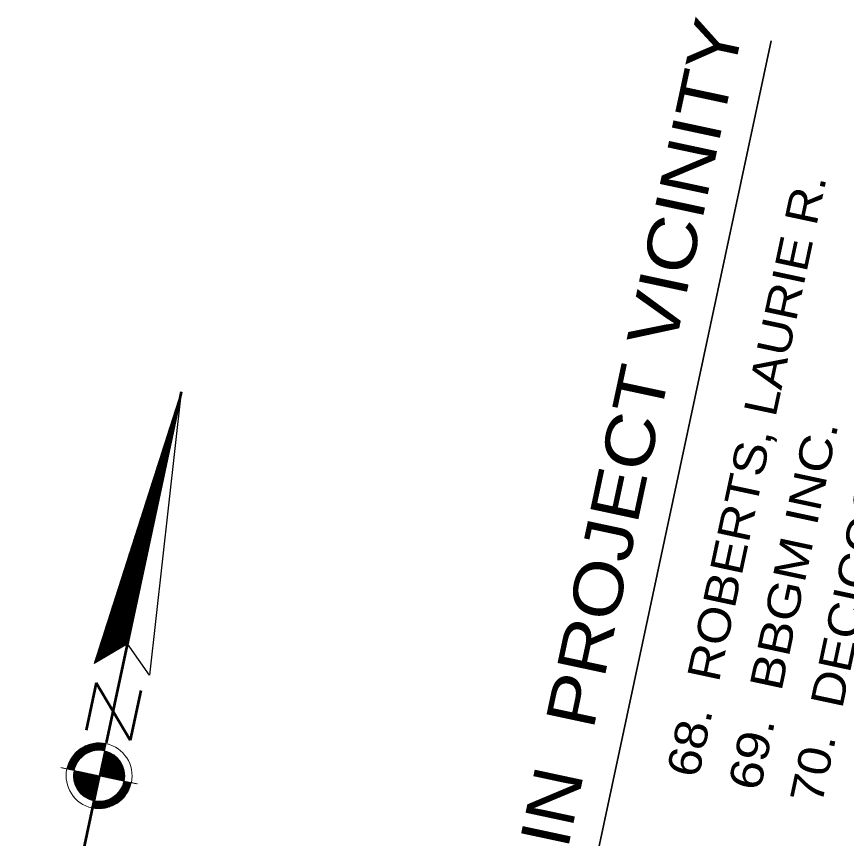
# Model space of a CAD drawing. Extents: x 2363411 to 2369702, y 6977197 to 6988655.
# Drawn here: x 2363737.9 to 2364093.2, y 6978563.1 to 6978914.9 of the extents above; entities that cross this region are included whole.
import ezdxf

# ---------------------------------------------------------------- set-up
doc = ezdxf.new("R2010")
doc.units = 0
doc.header["$LTSCALE"] = 5.6
doc.layers.add('1', color=7, linetype='Continuous', lineweight=25)
doc.layers.add('18', color=7, linetype='Continuous', lineweight=35)

msp = doc.modelspace()

# ---------------------------------------------------------------- linework, layer by layer
at = {"layer": '1', "lineweight": 53}
for p, q in [((2363808.35, 6978754.275), (2363776.257, 6978604.085)), ((2363772.027, 6978629.802), (2363767.673, 6978609.425)), ((2363772.027, 6978629.802), (2363786.549, 6978605.14)), ((2363791.108, 6978626.477), (2363786.549, 6978605.14)), ((2363773.247, 6978589.986), (2363737.89, 6978424.512))]:
    msp.add_line(p, q, dxfattribs=at)
at = {"layer": '1', "lineweight": 13}
for p, q in [((2363807.374, 6978751.23), (2363807.75, 6978751.475)), ((2363807.525, 6978751.705), (2363807.842, 6978751.909)), ((2363807.677, 6978752.18), (2363807.938, 6978752.345)), ((2363807.829, 6978752.648), (2363808.029, 6978752.781)), ((2363807.982, 6978753.125), (2363808.124, 6978753.215)), ((2363808.134, 6978753.598), (2363808.217, 6978753.651)), ((2363808.284, 6978754.071), (2363808.308, 6978754.088)), ((2363806.162, 6978747.443), (2363807.005, 6978747.987)), ((2363806.315, 6978747.918), (2363807.1, 6978748.425)), ((2363806.465, 6978748.391), (2363807.191, 6978748.862)), ((2363806.617, 6978748.864), (2363807.286, 6978749.297)), ((2363806.767, 6978749.337), (2363807.377, 6978749.732)), ((2363806.919, 6978749.81), (2363807.472, 6978750.166)), ((2363807.07, 6978750.285), (2363807.565, 6978750.602)), ((2363807.222, 6978750.757), (2363807.656, 6978751.039)), ((2363804.798, 6978743.182), (2363806.169, 6978744.069)), ((2363804.948, 6978743.655), (2363806.263, 6978744.505)), ((2363805.102, 6978744.13), (2363806.353, 6978744.938)), ((2363805.253, 6978744.603), (2363806.449, 6978745.378)), ((2363805.405, 6978745.075), (2363806.54, 6978745.812)), ((2363805.553, 6978745.549), (2363806.635, 6978746.248)), ((2363805.707, 6978746.021), (2363806.726, 6978746.683)), ((2363805.86, 6978746.496), (2363806.821, 6978747.117)), ((2363806.01, 6978746.971), (2363806.914, 6978747.555)), ((2363803.585, 6978739.394), (2363805.422, 6978740.582)), ((2363803.737, 6978739.866), (2363805.518, 6978741.02)), ((2363803.89, 6978740.339), (2363805.611, 6978741.454)), ((2363804.038, 6978740.813), (2363805.702, 6978741.891)), ((2363804.19, 6978741.285), (2363805.797, 6978742.326)), ((2363804.342, 6978741.76), (2363805.888, 6978742.763)), ((2363804.495, 6978742.233), (2363805.983, 6978743.199)), ((2363804.647, 6978742.707), (2363806.075, 6978743.635)), ((2363802.373, 6978735.605), (2363804.68, 6978737.1)), ((2363802.523, 6978736.078), (2363804.771, 6978737.535)), ((2363802.678, 6978736.553), (2363804.866, 6978737.971)), ((2363802.828, 6978737.026), (2363804.959, 6978738.407)), ((2363802.978, 6978737.499), (2363805.05, 6978738.841)), ((2363803.13, 6978737.971), (2363805.145, 6978739.277)), ((2363803.281, 6978738.446), (2363805.236, 6978739.712)), ((2363803.435, 6978738.919), (2363805.332, 6978740.15)), ((2363801.161, 6978731.817), (2363803.934, 6978733.615)), ((2363801.311, 6978732.292), (2363804.028, 6978734.049)), ((2363801.461, 6978732.763), (2363804.12, 6978734.486)), ((2363801.613, 6978733.238), (2363804.215, 6978734.921)), ((2363801.768, 6978733.71), (2363804.306, 6978735.356)), ((2363801.918, 6978734.185), (2363804.399, 6978735.792)), ((2363802.071, 6978734.66), (2363804.494, 6978736.23)), ((2363802.221, 6978735.133), (2363804.585, 6978736.664)), ((2363799.948, 6978728.028), (2363803.191, 6978730.129)), ((2363800.098, 6978728.501), (2363803.283, 6978730.568)), ((2363800.251, 6978728.976), (2363803.377, 6978731.002)), ((2363800.401, 6978729.449), (2363803.47, 6978731.438)), ((2363800.554, 6978729.924), (2363803.563, 6978731.872)), ((2363800.706, 6978730.398), (2363803.654, 6978732.307)), ((2363800.856, 6978730.871), (2363803.748, 6978732.747)), ((2363801.008, 6978731.344), (2363803.842, 6978733.179)), ((2363798.736, 6978724.24), (2363802.445, 6978726.646)), ((2363798.886, 6978724.713), (2363802.539, 6978727.08)), ((2363799.036, 6978725.186), (2363802.631, 6978727.518)), ((2363799.189, 6978725.661), (2363802.725, 6978727.95)), ((2363799.341, 6978726.133), (2363802.819, 6978728.388)), ((2363799.491, 6978726.608), (2363802.912, 6978728.823)), ((2363799.644, 6978727.083), (2363803.003, 6978729.259)), ((2363799.794, 6978727.558), (2363803.096, 6978729.695)), ((2363797.372, 6978719.981), (2363801.608, 6978722.722)), ((2363797.522, 6978720.454), (2363801.7, 6978723.163)), ((2363797.674, 6978720.924), (2363801.793, 6978723.597)), ((2363797.824, 6978721.399), (2363801.888, 6978724.033)), ((2363797.977, 6978721.874), (2363801.979, 6978724.467)), ((2363798.129, 6978722.347), (2363802.074, 6978724.903)), ((2363798.281, 6978722.821), (2363802.167, 6978725.339)), ((2363798.432, 6978723.295), (2363802.26, 6978725.773)), ((2363798.584, 6978723.767), (2363802.351, 6978726.21)), ((2363796.159, 6978716.19), (2363800.864, 6978719.239)), ((2363796.309, 6978716.665), (2363800.957, 6978719.675)), ((2363796.464, 6978717.138), (2363801.048, 6978720.111)), ((2363796.612, 6978717.613), (2363801.141, 6978720.546)), ((2363796.766, 6978718.085), (2363801.236, 6978720.981)), ((2363796.917, 6978718.56), (2363801.327, 6978721.418)), ((2363797.067, 6978719.033), (2363801.422, 6978721.852)), ((2363797.221, 6978719.506), (2363801.516, 6978722.29)), ((2363794.946, 6978712.402), (2363800.12, 6978715.755)), ((2363795.097, 6978712.877), (2363800.213, 6978716.191)), ((2363795.249, 6978713.349), (2363800.306, 6978716.625)), ((2363795.399, 6978713.823), (2363800.397, 6978717.062)), ((2363795.552, 6978714.297), (2363800.49, 6978717.496)), ((2363795.704, 6978714.772), (2363800.585, 6978717.934)), ((2363795.855, 6978715.245), (2363800.676, 6978718.369)), ((2363796.005, 6978715.718), (2363800.771, 6978718.804)), ((2363793.734, 6978708.613), (2363799.373, 6978712.27)), ((2363793.885, 6978709.088), (2363799.468, 6978712.706)), ((2363794.035, 6978709.563), (2363799.561, 6978713.14)), ((2363794.188, 6978710.038), (2363799.654, 6978713.576)), ((2363794.338, 6978710.511), (2363799.745, 6978714.013)), ((2363794.49, 6978710.984), (2363799.838, 6978714.449)), ((2363794.642, 6978711.456), (2363799.934, 6978714.885)), ((2363794.794, 6978711.929), (2363800.024, 6978715.319)), ((2363792.52, 6978704.827), (2363798.63, 6978708.786)), ((2363792.672, 6978705.3), (2363798.721, 6978709.221)), ((2363792.823, 6978705.775), (2363798.816, 6978709.656)), ((2363792.977, 6978706.247), (2363798.909, 6978710.091)), ((2363793.128, 6978706.722), (2363799.003, 6978710.529)), ((2363793.279, 6978707.193), (2363799.094, 6978710.963)), ((2363793.43, 6978707.668), (2363799.187, 6978711.4)), ((2363793.58, 6978708.141), (2363799.282, 6978711.833)), ((2363791.31, 6978701.038), (2363797.884, 6978705.303)), ((2363791.46, 6978701.513), (2363797.979, 6978705.735)), ((2363791.61, 6978701.986), (2363798.07, 6978706.171)), ((2363791.763, 6978702.461), (2363798.164, 6978706.605)), ((2363791.915, 6978702.934), (2363798.258, 6978707.041)), ((2363792.065, 6978703.407), (2363798.351, 6978707.478)), ((2363792.218, 6978703.881), (2363798.442, 6978707.912)), ((2363792.368, 6978704.355), (2363798.535, 6978708.35)), ((2363790.094, 6978697.253), (2363797.139, 6978701.817)), ((2363790.248, 6978697.725), (2363797.232, 6978702.252)), ((2363790.398, 6978698.198), (2363797.327, 6978702.685)), ((2363790.551, 6978698.673), (2363797.419, 6978703.124)), ((2363790.703, 6978699.145), (2363797.513, 6978703.558)), ((2363790.853, 6978699.618), (2363797.607, 6978703.994)), ((2363791.007, 6978700.091), (2363797.699, 6978704.428)), ((2363791.156, 6978700.566), (2363797.79, 6978704.863)), ((2363788.733, 6978692.989), (2363796.303, 6978697.895)), ((2363788.882, 6978693.466), (2363796.394, 6978698.33)), ((2363789.034, 6978693.937), (2363796.488, 6978698.766)), ((2363789.186, 6978694.411), (2363796.581, 6978699.202)), ((2363789.337, 6978694.886), (2363796.675, 6978699.636)), ((2363789.49, 6978695.357), (2363796.767, 6978700.075)), ((2363789.641, 6978695.83), (2363796.862, 6978700.508)), ((2363789.793, 6978696.303), (2363796.955, 6978700.945)), ((2363789.945, 6978696.777), (2363797.046, 6978701.379)), ((2363787.521, 6978689.202), (2363795.559, 6978694.41)), ((2363787.669, 6978689.676), (2363795.652, 6978694.846)), ((2363787.824, 6978690.15), (2363795.743, 6978695.281)), ((2363787.973, 6978690.621), (2363795.836, 6978695.719)), ((2363788.126, 6978691.096), (2363795.929, 6978696.153)), ((2363788.278, 6978691.57), (2363796.024, 6978696.589)), ((2363788.429, 6978692.043), (2363796.115, 6978697.023)), ((2363788.579, 6978692.516), (2363796.21, 6978697.459)), ((2363786.306, 6978685.412), (2363794.812, 6978690.925)), ((2363786.459, 6978685.887), (2363794.907, 6978691.361)), ((2363786.609, 6978686.362), (2363795, 6978691.797)), ((2363786.761, 6978686.834), (2363795.092, 6978692.233)), ((2363786.913, 6978687.307), (2363795.185, 6978692.671)), ((2363787.064, 6978687.78), (2363795.278, 6978693.104)), ((2363787.216, 6978688.255), (2363795.373, 6978693.539)), ((2363787.366, 6978688.728), (2363795.464, 6978693.976)), ((2363785.094, 6978681.626), (2363794.07, 6978687.441)), ((2363785.244, 6978682.099), (2363794.161, 6978687.875)), ((2363785.396, 6978682.571), (2363794.256, 6978688.313)), ((2363785.549, 6978683.048), (2363794.349, 6978688.747)), ((2363785.699, 6978683.517), (2363794.44, 6978689.184)), ((2363785.849, 6978683.992), (2363794.533, 6978689.618)), ((2363786.004, 6978684.466), (2363794.626, 6978690.052)), ((2363786.156, 6978684.941), (2363794.721, 6978690.49)), ((2363783.878, 6978677.84), (2363793.323, 6978683.956)), ((2363784.035, 6978678.314), (2363793.418, 6978684.392)), ((2363784.182, 6978678.785), (2363793.509, 6978684.826)), ((2363784.337, 6978679.259), (2363793.605, 6978685.264)), ((2363784.487, 6978679.733), (2363793.697, 6978685.696)), ((2363784.637, 6978680.206), (2363793.788, 6978686.133)), ((2363784.792, 6978680.68), (2363793.882, 6978686.571)), ((2363784.942, 6978681.153), (2363793.974, 6978687.003)), ((2363782.667, 6978674.049), (2363792.578, 6978680.47)), ((2363782.82, 6978674.522), (2363792.671, 6978680.906)), ((2363782.972, 6978674.996), (2363792.767, 6978681.342)), ((2363783.122, 6978675.469), (2363792.857, 6978681.777)), ((2363783.275, 6978675.946), (2363792.953, 6978682.215)), ((2363783.425, 6978676.419), (2363793.045, 6978682.647)), ((2363783.577, 6978676.892), (2363793.137, 6978683.085)), ((2363783.73, 6978677.364), (2363793.23, 6978683.52)), ((2363781.305, 6978669.789), (2363791.743, 6978676.55)), ((2363781.455, 6978670.261), (2363791.834, 6978676.987)), ((2363781.608, 6978670.735), (2363791.929, 6978677.421)), ((2363781.76, 6978671.208), (2363792.02, 6978677.859)), ((2363781.91, 6978671.681), (2363792.115, 6978678.293)), ((2363782.06, 6978672.156), (2363792.206, 6978678.73)), ((2363782.213, 6978672.629), (2363792.301, 6978679.165)), ((2363782.365, 6978673.103), (2363792.394, 6978679.599)), ((2363782.517, 6978673.576), (2363792.485, 6978680.036)), ((2363780.091, 6978666.001), (2363790.998, 6978673.065)), ((2363780.243, 6978666.474), (2363791.092, 6978673.503)), ((2363780.393, 6978666.945), (2363791.182, 6978673.937)), ((2363780.547, 6978667.419), (2363791.278, 6978674.373)), ((2363780.696, 6978667.895), (2363791.369, 6978674.81)), ((2363780.848, 6978668.368), (2363791.464, 6978675.244)), ((2363781.003, 6978668.842), (2363791.555, 6978675.68)), ((2363781.153, 6978669.315), (2363791.65, 6978676.116)), ((2363778.877, 6978662.213), (2363790.251, 6978669.58)), ((2363779.031, 6978662.688), (2363790.346, 6978670.015)), ((2363779.181, 6978663.161), (2363790.44, 6978670.452)), ((2363779.333, 6978663.633), (2363790.53, 6978670.886)), ((2363779.485, 6978664.106), (2363790.626, 6978671.322)), ((2363779.638, 6978664.579), (2363790.717, 6978671.759)), ((2363779.791, 6978665.055), (2363790.812, 6978672.192)), ((2363779.941, 6978665.528), (2363790.903, 6978672.631)), ((2363777.664, 6978658.425), (2363789.509, 6978666.096)), ((2363777.818, 6978658.897), (2363789.6, 6978666.532)), ((2363777.969, 6978659.372), (2363789.695, 6978666.966)), ((2363778.121, 6978659.845), (2363789.786, 6978667.403)), ((2363778.272, 6978660.32), (2363789.879, 6978667.839)), ((2363778.424, 6978660.793), (2363789.974, 6978668.275)), ((2363778.576, 6978661.267), (2363790.065, 6978668.709)), ((2363778.726, 6978661.738), (2363790.16, 6978669.145)), ((2363776.452, 6978654.636), (2363788.762, 6978662.611)), ((2363776.604, 6978655.109), (2363788.858, 6978663.048)), ((2363776.756, 6978655.582), (2363788.949, 6978663.483)), ((2363776.907, 6978656.057), (2363789.043, 6978663.917)), ((2363777.061, 6978656.529), (2363789.135, 6978664.353)), ((2363777.211, 6978657.004), (2363789.228, 6978664.79)), ((2363777.363, 6978657.477), (2363789.323, 6978665.225)), ((2363777.516, 6978657.949), (2363789.414, 6978665.66)), ((2363775.239, 6978650.848), (2363788.02, 6978659.127)), ((2363775.393, 6978651.32), (2363788.111, 6978659.563)), ((2363775.544, 6978651.795), (2363788.206, 6978659.997)), ((2363775.695, 6978652.27), (2363788.299, 6978660.433)), ((2363775.847, 6978652.743), (2363788.392, 6978660.867)), ((2363775.999, 6978653.218), (2363788.483, 6978661.304)), ((2363776.151, 6978653.688), (2363788.577, 6978661.742)), ((2363776.304, 6978654.163), (2363788.672, 6978662.178)), ((2363774.029, 6978647.061), (2363787.273, 6978655.642)), ((2363774.18, 6978647.536), (2363787.368, 6978656.075)), ((2363774.332, 6978648.007), (2363787.459, 6978656.512)), ((2363774.482, 6978648.482), (2363787.554, 6978656.948)), ((2363774.635, 6978648.956), (2363787.647, 6978657.384)), ((2363774.787, 6978649.429), (2363787.741, 6978657.82)), ((2363774.937, 6978649.902), (2363787.832, 6978658.257)), ((2363775.091, 6978650.372), (2363787.925, 6978658.691)), ((2363772.664, 6978642.798), (2363786.438, 6978651.721)), ((2363772.817, 6978643.271), (2363786.528, 6978652.156)), ((2363772.967, 6978643.746), (2363786.622, 6978652.592)), ((2363773.117, 6978644.219), (2363786.716, 6978653.026)), ((2363773.27, 6978644.693), (2363786.808, 6978653.465)), ((2363773.422, 6978645.166), (2363786.903, 6978653.9)), ((2363773.575, 6978645.641), (2363786.996, 6978654.335)), ((2363773.727, 6978646.113), (2363787.089, 6978654.771)), ((2363773.877, 6978646.586), (2363787.18, 6978655.203)), ((2363771.45, 6978639.01), (2363785.693, 6978648.238)), ((2363771.605, 6978639.484), (2363785.786, 6978648.672)), ((2363771.755, 6978639.957), (2363785.877, 6978649.109)), ((2363771.907, 6978640.432), (2363785.97, 6978649.545)), ((2363772.057, 6978640.905), (2363786.065, 6978649.977)), ((2363772.21, 6978641.378), (2363786.156, 6978650.415)), ((2363772.36, 6978641.851), (2363786.251, 6978650.849)), ((2363772.512, 6978642.323), (2363786.344, 6978651.285)), ((2363771.147, 6978638.062), (2363785.505, 6978647.366)), ((2363771.3, 6978638.537), (2363785.6, 6978647.8)), ((2363777.979, 6978642.112), (2363785.414, 6978646.929)), ((2363759.909, 6978594.501), (2363774.54, 6978603.982)), ((2363760.085, 6978594.991), (2363774.02, 6978604.019)), ((2363760.294, 6978595.5), (2363773.472, 6978604.04)), ((2363760.532, 6978596.03), (2363772.888, 6978604.034)), ((2363760.815, 6978596.588), (2363772.263, 6978604.008)), ((2363761.146, 6978597.182), (2363771.586, 6978603.942)), ((2363761.547, 6978597.814), (2363770.843, 6978603.837)), ((2363762.06, 6978598.52), (2363769.993, 6978603.665)), ((2363762.724, 6978599.327), (2363768.99, 6978603.384)), ((2363763.763, 6978600.373), (2363767.6, 6978602.863)), ((2363769.083, 6978600.069), (2363775.035, 6978603.927)), ((2363770.324, 6978600.497), (2363775.511, 6978603.858)), ((2363771.221, 6978600.702), (2363775.962, 6978603.776)), ((2363771.976, 6978600.819), (2363776.135, 6978603.514)), ((2363772.642, 6978600.873), (2363776.041, 6978603.076)), ((2363773.247, 6978600.889), (2363775.949, 6978602.641)), ((2363773.804, 6978600.876), (2363775.858, 6978602.207)), ((2363776.183, 6978603.731), (2363775.526, 6978600.652)), ((2363774.236, 6978594.626), (2363780.13, 6978598.445)), ((2363774.322, 6978600.838), (2363775.765, 6978601.771)), ((2363774.332, 6978595.064), (2363779.869, 6978598.65)), ((2363774.422, 6978595.498), (2363779.599, 6978598.851)), ((2363774.518, 6978595.934), (2363779.32, 6978599.048)), ((2363774.61, 6978596.368), (2363779.029, 6978599.233)), ((2363774.704, 6978596.805), (2363778.728, 6978599.413)), ((2363774.795, 6978597.243), (2363778.417, 6978599.588)), ((2363774.808, 6978600.777), (2363775.67, 6978601.337)), ((2363774.888, 6978597.675), (2363778.093, 6978599.754)), ((2363774.983, 6978598.111), (2363777.76, 6978599.911)), ((2363775.074, 6978598.548), (2363777.414, 6978600.06)), ((2363775.169, 6978598.983), (2363777.054, 6978600.205)), ((2363775.262, 6978599.418), (2363776.677, 6978600.334)), ((2363775.272, 6978600.698), (2363775.578, 6978600.898)), ((2363775.355, 6978599.854), (2363776.283, 6978600.455)), ((2363775.446, 6978600.29), (2363775.876, 6978600.567)), ((2363759.514, 6978593.121), (2363764.257, 6978596.194)), ((2363759.623, 6978593.566), (2363764.817, 6978596.931)), ((2363759.682, 6978592.854), (2363763.838, 6978595.545)), ((2363759.754, 6978594.025), (2363765.701, 6978597.879)), ((2363760.118, 6978592.761), (2363763.517, 6978594.961)), ((2363773.308, 6978590.272), (2363782.291, 6978596.094)), ((2363773.36, 6978589.931), (2363782.461, 6978595.828)), ((2363773.4, 6978590.706), (2363782.108, 6978596.349)), ((2363773.492, 6978591.144), (2363781.919, 6978596.604)), ((2363773.585, 6978591.579), (2363781.727, 6978596.852)), ((2363773.68, 6978592.014), (2363781.521, 6978597.096)), ((2363773.771, 6978592.449), (2363781.31, 6978597.334)), ((2363773.796, 6978589.838), (2363782.629, 6978595.561)), ((2363773.866, 6978592.887), (2363781.09, 6978597.567)), ((2363773.959, 6978593.319), (2363780.863, 6978597.796)), ((2363774.052, 6978593.757), (2363780.628, 6978598.017)), ((2363774.143, 6978594.192), (2363780.384, 6978598.233)), ((2363774.23, 6978589.743), (2363782.785, 6978595.286)), ((2363774.668, 6978589.652), (2363782.936, 6978595.009)), ((2363759.484, 6978592.896), (2363756.771, 6978593.474)), ((2363757.127, 6978593.4), (2363783.865, 6978587.687)), ((2363762.543, 6978592.242), (2363759.463, 6978592.901)), ((2363760.552, 6978592.668), (2363763.256, 6978594.418)), ((2363760.99, 6978592.574), (2363763.043, 6978593.903)), ((2363761.425, 6978592.481), (2363762.866, 6978593.415)), ((2363761.861, 6978592.388), (2363762.721, 6978592.947)), ((2363765.207, 6978591.673), (2363762.235, 6978589.748)), ((2363764.771, 6978591.766), (2363762.238, 6978590.123)), ((2363764.337, 6978591.859), (2363762.248, 6978590.508)), ((2363765.643, 6978591.578), (2363762.251, 6978589.382)), ((2363763.903, 6978591.952), (2363762.27, 6978590.898)), ((2363766.08, 6978591.487), (2363762.277, 6978589.023)), ((2363762.297, 6978592.293), (2363762.601, 6978592.492)), ((2363766.516, 6978591.394), (2363762.312, 6978588.67)), ((2363763.465, 6978592.046), (2363762.313, 6978591.3)), ((2363766.952, 6978591.3), (2363762.359, 6978588.324)), ((2363763.03, 6978592.138), (2363762.375, 6978591.714)), ((2363762.594, 6978592.23), (2363762.452, 6978592.139)), ((2363789.283, 6978586.529), (2363762.543, 6978592.242)), ((2363775.102, 6978589.559), (2363783.081, 6978594.726)), ((2363775.537, 6978589.466), (2363783.213, 6978594.438)), ((2363775.975, 6978589.373), (2363783.341, 6978594.145)), ((2363776.407, 6978589.28), (2363783.459, 6978593.848)), ((2363776.845, 6978589.187), (2363783.568, 6978593.542)), ((2363777.279, 6978589.092), (2363783.674, 6978593.233)), ((2363777.716, 6978589.001), (2363783.764, 6978592.919)), ((2363778.152, 6978588.907), (2363783.849, 6978592.599)), ((2363778.586, 6978588.815), (2363783.927, 6978592.273)), ((2363779.022, 6978588.721), (2363783.993, 6978591.94)), ((2363779.458, 6978588.628), (2363784.051, 6978591.602)), ((2363767.386, 6978591.208), (2363762.416, 6978587.989)), ((2363767.822, 6978591.114), (2363762.479, 6978587.654)), ((2363768.257, 6978591.022), (2363762.559, 6978587.328)), ((2363768.692, 6978590.927), (2363762.644, 6978587.01)), ((2363769.129, 6978590.835), (2363762.736, 6978586.693)), ((2363769.563, 6978590.742), (2363762.839, 6978586.387)), ((2363769.999, 6978590.649), (2363762.949, 6978586.081)), ((2363770.436, 6978590.556), (2363763.067, 6978585.78)), ((2363770.87, 6978590.463), (2363763.197, 6978585.489)), ((2363771.308, 6978590.37), (2363763.328, 6978585.203)), ((2363771.74, 6978590.275), (2363763.474, 6978584.918)), ((2363772.176, 6978590.184), (2363763.623, 6978584.641)), ((2363772.613, 6978590.091), (2363763.779, 6978584.366)), ((2363773.049, 6978589.998), (2363763.945, 6978584.101)), ((2363773.103, 6978589.657), (2363764.115, 6978583.834)), ((2363773.01, 6978589.223), (2363764.298, 6978583.578)), ((2363772.917, 6978588.787), (2363764.489, 6978583.323)), ((2363772.824, 6978588.352), (2363764.681, 6978583.075)), ((2363772.73, 6978587.912), (2363764.887, 6978582.833)), ((2363773.17, 6978589.972), (2363773.072, 6978589.993)), ((2363773.238, 6978589.957), (2363773.336, 6978589.936)), ((2363779.895, 6978588.535), (2363784.097, 6978591.259)), ((2363780.33, 6978588.44), (2363784.13, 6978590.907)), ((2363780.765, 6978588.349), (2363784.159, 6978590.546)), ((2363781.201, 6978588.256), (2363784.173, 6978590.179)), ((2363781.635, 6978588.163), (2363784.172, 6978589.803)), ((2363782.073, 6978588.069), (2363784.16, 6978589.423)), ((2363782.508, 6978587.977), (2363784.136, 6978589.032)), ((2363782.944, 6978587.883), (2363784.095, 6978588.629)), ((2363783.38, 6978587.788), (2363784.033, 6978588.215)), ((2363783.814, 6978587.698), (2363783.959, 6978587.791)), ((2363772.638, 6978587.48), (2363765.098, 6978582.593)), ((2363772.544, 6978587.044), (2363765.318, 6978582.36)), ((2363772.451, 6978586.608), (2363765.546, 6978582.134)), ((2363772.358, 6978586.171), (2363765.782, 6978581.911)), ((2363772.263, 6978585.736), (2363766.026, 6978581.693)), ((2363772.172, 6978585.299), (2363766.28, 6978581.484)), ((2363772.078, 6978584.863), (2363766.54, 6978581.275)), ((2363771.986, 6978584.429), (2363766.811, 6978581.078)), ((2363786.502, 6978585.43), (2363771.871, 6978575.947)), ((2363786.323, 6978584.938), (2363772.389, 6978575.91)), ((2363786.116, 6978584.426), (2363772.936, 6978575.889)), ((2363786.654, 6978585.904), (2363780.705, 6978582.05)), ((2363786.785, 6978586.363), (2363781.591, 6978582.998)), ((2363786.895, 6978586.808), (2363782.151, 6978583.733)), ((2363786.724, 6978587.074), (2363782.57, 6978584.382)), ((2363786.29, 6978587.168), (2363782.893, 6978584.966)), ((2363785.854, 6978587.262), (2363783.152, 6978585.509)), ((2363785.418, 6978587.355), (2363783.367, 6978586.024)), ((2363784.984, 6978587.448), (2363783.541, 6978586.512)), ((2363784.548, 6978587.541), (2363783.686, 6978586.984)), ((2363784.112, 6978587.634), (2363783.807, 6978587.435)), ((2363783.865, 6978587.687), (2363786.946, 6978587.028)), ((2363786.924, 6978587.033), (2363789.639, 6978586.453)), ((2363771.893, 6978583.994), (2363767.088, 6978580.882)), ((2363771.799, 6978583.556), (2363767.38, 6978580.695)), ((2363771.707, 6978583.124), (2363767.68, 6978580.514)), ((2363771.611, 6978582.686), (2363767.989, 6978580.339)), ((2363771.52, 6978582.252), (2363768.313, 6978580.174)), ((2363771.427, 6978581.816), (2363768.65, 6978580.016)), ((2363771.334, 6978581.379), (2363768.996, 6978579.864)), ((2363771.241, 6978580.945), (2363769.356, 6978579.722)), ((2363785.876, 6978583.897), (2363773.518, 6978575.894)), ((2363785.593, 6978583.337), (2363774.146, 6978575.921)), ((2363785.26, 6978582.748), (2363774.822, 6978575.985)), ((2363784.861, 6978582.113), (2363775.565, 6978576.094)), ((2363784.35, 6978581.406), (2363776.415, 6978576.269)), ((2363771.148, 6978580.509), (2363769.731, 6978579.593)), ((2363771.055, 6978580.075), (2363770.123, 6978579.472)), ((2363770.227, 6978576.196), (2363770.885, 6978579.277)), ((2363774.43, 6978579.108), (2363770.273, 6978576.413)), ((2363773.766, 6978579.054), (2363770.367, 6978576.851)), ((2363775.189, 6978579.224), (2363770.446, 6978576.153)), ((2363773.161, 6978579.038), (2363770.46, 6978577.288)), ((2363770.96, 6978579.639), (2363770.53, 6978579.361)), ((2363772.604, 6978579.053), (2363770.553, 6978577.722)), ((2363772.086, 6978579.09), (2363770.646, 6978578.158)), ((2363771.596, 6978579.151), (2363770.739, 6978578.592)), ((2363771.138, 6978579.229), (2363770.832, 6978579.028)), ((2363776.086, 6978579.429), (2363770.897, 6978576.071)), ((2363777.323, 6978579.858), (2363771.371, 6978576.003)), ((2363783.684, 6978580.6), (2363777.42, 6978576.543)), ((2363782.647, 6978579.553), (2363778.806, 6978577.065))]:
    msp.add_line(p, q, dxfattribs=at)
msp.add_lwpolyline([(2363771.137, 6978638.025), (2363785.32, 6978646.5), (2363808.35, 6978754.275)], close=True, dxfattribs=at)
at = {"layer": '1'}
msp.add_lwpolyline([(2363794.805, 6978632.97), (2363785.32, 6978646.5), (2363808.35, 6978754.275)], close=True, dxfattribs=at)
at = {"layer": '1', "lineweight": 13}
for points in [[(2363783.935, 6978587.67), (2363773.238, 6978589.957), (2363775.526, 6978600.652)], [(2363762.473, 6978592.257), (2363773.17, 6978589.972), (2363770.885, 6978579.277)]]:
    msp.add_lwpolyline(points, dxfattribs=at)
for centre, radius, start, end in [((2363773.239, 6978589.956), 14.087, 77.93906, 167.93906), ((2363773.239, 6978589.956), 14.087, 347.93906, 77.75402), ((2363773.239, 6978589.956), 10.937, 77.93906, 167.93906), ((2363773.239, 6978589.956), 10.937, 347.93906, 77.93906), ((2363773.169, 6978589.971), 14.087, 167.93906, 257.75402), ((2363773.169, 6978589.971), 10.937, 167.93906, 257.93906), ((2363773.169, 6978589.971), 14.087, 257.93906, 347.93906), ((2363773.169, 6978589.971), 10.937, 257.93906, 347.93906)]:
    msp.add_arc(centre, radius, start, end, dxfattribs=at)
at = {"layer": '18'}
msp.add_line((2363910.069, 6978198.379), (2364060.962, 6978904.578), dxfattribs=at)

# ---------------------------------------------------------------- texts
for s, height, width, p in [('PROPERTY OWNERS IN  PROJECT VICINITY', 21, 1.2, (2363899.459, 6978210.017)), ('68.  ROBERTS, LAURIE R.', 14, 1.15, (2364029.752, 6978588.555)), ('70.  DECICCO, PETER A.', 14, 1.15, (2364082.561, 6978577.272)), ('69.  BBGM INC.', 14, 1.2, (2364056.156, 6978582.914))]:
    msp.add_text(s, height=height, rotation=77.939, dxfattribs=dict(at, width=width)).set_placement(p)

doc.saveas('drawing.dxf')
